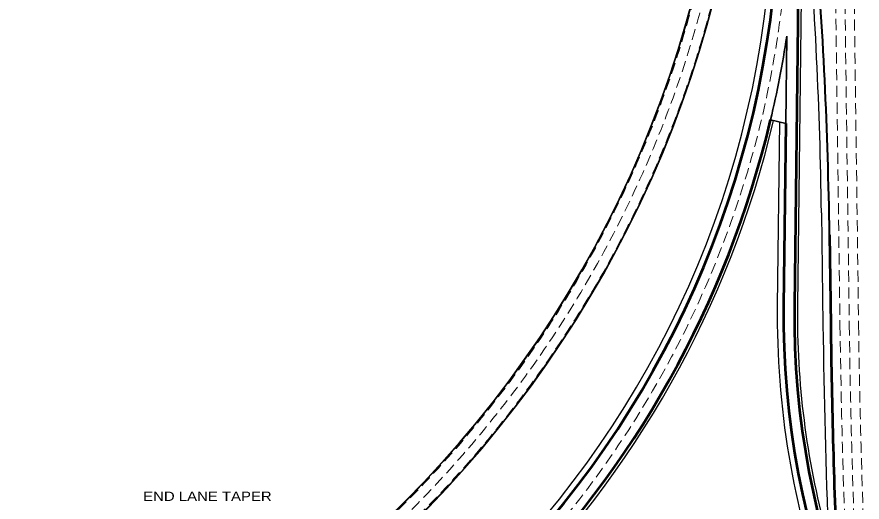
# Model space of a CAD drawing. Extents: x 2326434 to 2368642, y 6985225 to 6995090.
# Drawn here: x 2332211 to 2333302, y 6991957 to 6992583 of the extents above; entities that cross this region are included whole.
import ezdxf

# ---------------------------------------------------------------- set-up
doc = ezdxf.new("R2010")
doc.units = 0
doc.header["$LTSCALE"] = 4.8
doc.linetypes.add('MEDIUM_DASHED', pattern=[4.5, 3, -1.5])
for name, color, linetype, lineweight in [('10', 7, 'Continuous', 35), ('26', 7, 'Continuous', 25), ('27', 7, 'Continuous', 25), ('28', 7, 'Continuous', 25), ('5', 7, 'Continuous', 25), ('50', 7, 'MEDIUM_DASHED', 13)]:
    doc.layers.add(name, color=color, linetype=linetype, lineweight=lineweight)

msp = doc.modelspace()

# ---------------------------------------------------------------- linework, layer by layer
at = {"layer": '10'}
for p in [(2333204.312, 6992557.803), (2333183.524, 6992449.879)]:
    msp.add_line(p, (2333202.985, 6992445.268), dxfattribs=at)
for radius, start, end in [(1265.239, 273.05017, 273.05017), (1297.239, 346.66935, 351.52512)]:
    msp.add_arc((2331921.237, 6992748.984), radius, start, end, dxfattribs=at)
at = {"layer": '26'}
msp.add_line((2333249.149, 6992329.841), (2333251.078, 6992185.573), dxfattribs=at)
at = {"layer": '26', "lineweight": 53}
msp.add_line((2333259.527, 6992301.655), (2333261.077, 6992185.707), dxfattribs=at)
at = {"layer": '26'}
msp.add_arc((2344767.204, 6992339.592), 11517.156, 180.76624, 182.1538, dxfattribs=at)
at = {"layer": '26', "lineweight": 53}
msp.add_arc((2344767.204, 6992339.592), 11507.156, 180.76624, 182.34602, dxfattribs=at)
at = {"layer": '27', "lineweight": 53}
for p, q in [((2333220.854, 6992773.335), (2333214.21, 6992209.921)), ((2333202.985, 6992445.268), (2333200.211, 6992210.086))]:
    msp.add_line(p, q, dxfattribs=at)
at = {"layer": '27'}
for p, q in [((2333224.854, 6992773.288), (2333218.21, 6992209.874)), ((2333195.006, 6992447.158), (2333192.212, 6992210.181))]:
    msp.add_line(p, q, dxfattribs=at)
for centre, radius, start, end in [((2331921.237, 6992748.984), 1265.239, 273.05017, 359.32438), ((2327520.083, 6992253.219), 5729.578, 0.76624, 4.76624), ((2331921.237, 6992748.984), 1301.239, 283.0472, 346.66935), ((2334291.484, 6992197.218), 1099.348, 179.32439, 199.55249), ((2334291.484, 6992197.218), 1073.348, 179.32439, 195.11064)]:
    msp.add_arc(centre, radius, start, end, dxfattribs=at)
at = {"layer": '27', "lineweight": 53}
for centre, radius, start, end in [((2331921.237, 6992748.984), 1273.239, 273.05017, 359.32438), ((2331921.237, 6992748.984), 1297.239, 283.52851, 346.66935), ((2334291.484, 6992197.218), 1091.348, 179.32439, 270.28461), ((2334291.484, 6992197.218), 1077.348, 179.32439, 270.28461)]:
    msp.add_arc(centre, radius, start, end, dxfattribs=at)
at = {"layer": '27', "lineweight": 40}
msp.add_arc((2327530.461, 6992225.034), 5729.578, 0.76624, 4.76624, dxfattribs=at)
at = {"layer": '28'}
for radius, start in [(1431.895, 270.53549), (1432.395, 270.53549), (1458.395, 271.68649), (1458.895, 271.68649)]:
    msp.add_arc((2331697.424, 6992968.484), radius, start, 359.76624, dxfattribs=at)
at = {"layer": '50'}
for p, q in [((2333267.682, 6993486.514), (2333285.075, 6992186.028)), ((2333279.681, 6993486.675), (2333297.074, 6992186.188)), ((2333267.225, 6992623.391), (2333273.076, 6992185.867))]:
    msp.add_line(p, q, dxfattribs=at)
for centre, radius, start, end in [((2331697.424, 6992968.484), 1433.395, 270.53549, 359.76624), ((2331697.424, 6992968.484), 1445.395, 270.53549, 359.76624), ((2331697.424, 6992968.484), 1457.395, 271.68649, 359.76624), ((2331921.237, 6992748.984), 1285.675, 311.25764, 359.32438), ((2344767.204, 6992339.592), 11495.156, 180.76624, 183.88451), ((2344767.204, 6992339.592), 11483.156, 180.76624, 183.88451), ((2344767.204, 6992339.592), 11471.156, 180.76624, 183.88451)]:
    msp.add_arc(centre, radius, start, end, dxfattribs=at)

# ---------------------------------------------------------------- texts
at = {"layer": '5', "width": 1.2}
msp.add_text('END LANE TAPER', height=12, dxfattribs=at).set_placement((2332373.854, 6991958.395))

doc.saveas('drawing.dxf')
